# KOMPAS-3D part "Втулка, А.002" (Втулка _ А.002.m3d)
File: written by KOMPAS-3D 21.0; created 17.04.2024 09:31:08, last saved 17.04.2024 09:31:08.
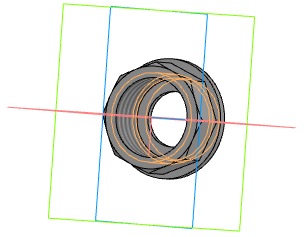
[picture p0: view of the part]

Document properties: Автор: Admin; Полное имя файла: C:\Users\wsr\Desktop\Чертежи\Детали\Втулка _ А.002.m3d

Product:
- Part/product: Втулка  | designation А.002
    Масса: 0.02545

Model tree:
1. Эскиз:1
2. Элемент выдавливания:1
     Расстояние 1 = 8
3. Эскиз:2  (with: Элемент выдавливания:1)
4. Элемент выдавливания:2
     Расстояние 1 = 2
5. Эскиз:3  (with: Элемент выдавливания:2)
6. Элемент выдавливания:3
     Расстояние 1 = 1
7. Эскиз:4  (with: Элемент выдавливания:3)
8. Элемент выдавливания:4
     Расстояние 1 = 5
9. Условное изображение резьбы:1  (with: Элемент выдавливания:4)  (labels: M22; cil0_24705-2004 coarse)
     Длина резьбы = 5; Шаг резьбы = 2.5; Номинальный диаметр резьбы = 22
10. Подгонка:1  (with: Элемент выдавливания:4)
11. Фаска:1  (with: Элемент выдавливания:4)
     Угол = 45; Длина 1 = 1; Длина 2 = 1
12. Эскиз:5  (with: Элемент выдавливания:1)
13. Элемент вращения:1  (with: Элемент выдавливания:4)
     Угол 1 = 360
14. Эскиз:6  (with: Элемент выдавливания:4, Фаска:1)
15. Элемент выдавливания:5
     Расстояние 2 = 3.5
16. Эскиз:7  (with: Элемент выдавливания:5)
17. Элемент выдавливания:6
     Расстояние 2 = 80
18. Эскиз:8  (with: Элемент выдавливания:1, Элемент выдавливания:6)
19. Элемент выдавливания:7
     Расстояние 2 = 11
20. Условное изображение резьбы:2  (with: Элемент выдавливания:7)
     Длина резьбы = 11; Шаг резьбы = 1.814; Номинальный диаметр резьбы = 20.955
21. Подгонка:2  (with: Элемент выдавливания:7)

Expressions: 24/2; G 1/2; cil2_6357-81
